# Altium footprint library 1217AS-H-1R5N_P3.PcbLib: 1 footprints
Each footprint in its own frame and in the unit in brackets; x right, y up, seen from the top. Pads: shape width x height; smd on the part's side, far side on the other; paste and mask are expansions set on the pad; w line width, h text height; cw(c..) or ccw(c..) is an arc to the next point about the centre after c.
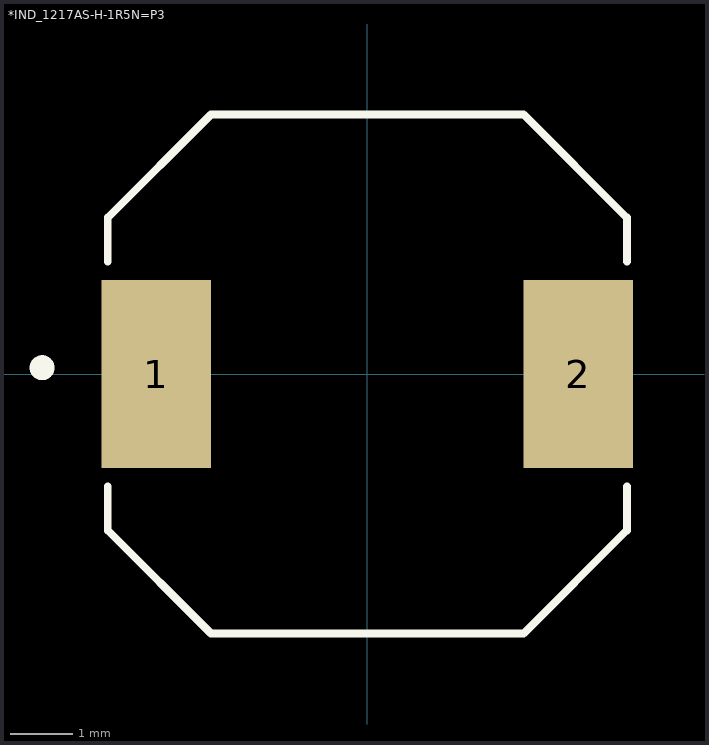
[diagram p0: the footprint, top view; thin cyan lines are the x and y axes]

## *IND_1217AS-H-1R5N=P3 [mm]
pads (2):
  rect 1.75x3 smd: 1(-3.375,0) 2(3.375,0)
Top Overlay:
  circle w0.2: c-5.2,0.1 r0.1
  lines w0.127: -4.15,-1.8 -4.15,-2.5 -2.5,-4.15 2.5,-4.15 4.15,-2.5 4.15,-1.8 ; -4.15,1.8 -4.15,2.5 -2.5,4.15 2.5,4.15 4.15,2.5 4.15,1.8 ; -0.5,4.15 0.5,4.15 ; -0.5,-4.15 0.5,-4.15 -0.5,-4.15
